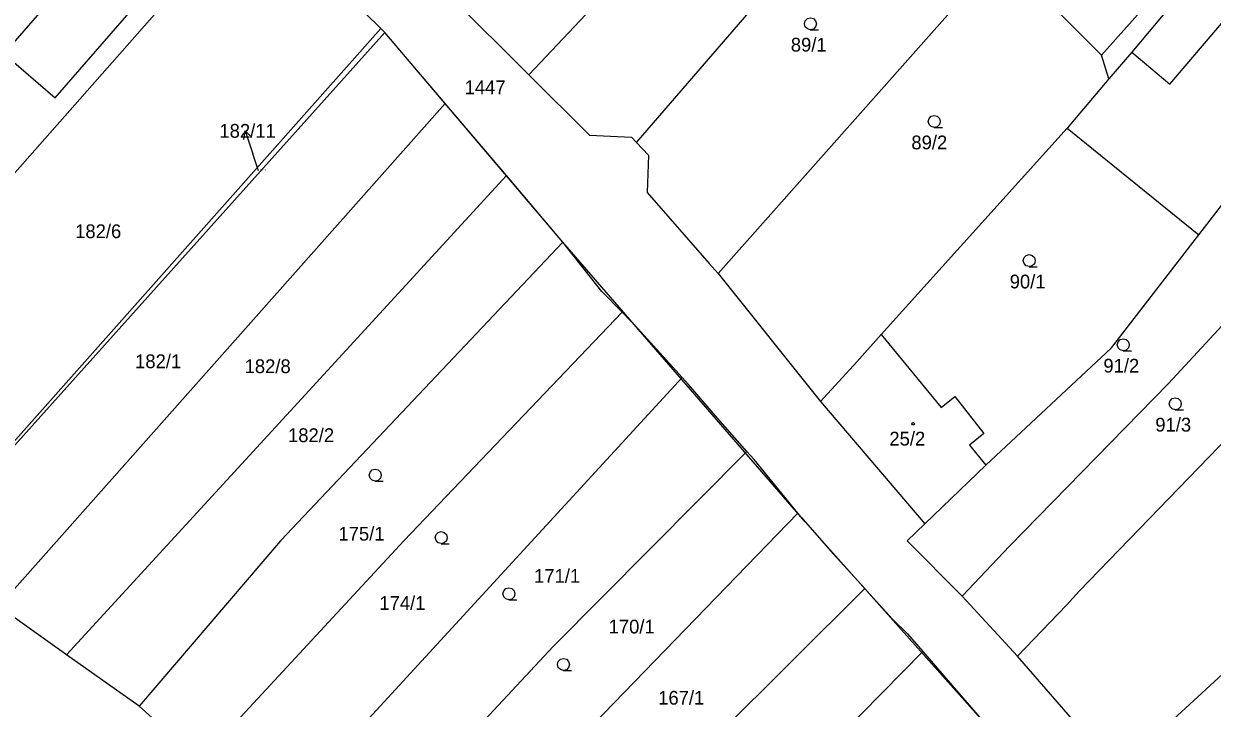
# Model space of a CAD drawing. Extents: x -580630 to -576196, y -1189024 to -1183567.
# Drawn here: x -578839.8 to -578693.1, y -1185934.4 to -1185849.8 of the extents above; entities that cross this region are included whole.
import ezdxf

# ---------------------------------------------------------------- set-up
doc = ezdxf.new("R2010")
doc.units = 0
for name, color, linetype in [('Vrstva 1', 7, 'Continuous'), ('Vrstva 16', 7, 'Continuous'), ('Vrstva 18', 7, 'Continuous'), ('Vrstva 19', 7, 'Continuous'), ('Vrstva 25', 7, 'Continuous'), ('Vrstva 4', 7, 'Continuous'), ('Vrstva 6', 7, 'Continuous'), ('Vrstva 63', 7, 'Continuous')]:
    doc.layers.add(name, color=color, linetype=linetype)

msp = doc.modelspace()

# ---------------------------------------------------------------- linework, layer by layer
at = {"layer": 'Vrstva 1'}
for p, q in [((-578764.13, -1185864.5), (-578737.1, -1185833.11)), ((-578715.81, -1185837.51), (-578754.08, -1185880.68)), ((-578835.92, -1185858.99), (-578820.89, -1185841.68)), ((-578795.7, -1185850.39), (-578805.13, -1185841.14)), ((-578842.2, -1185853.55), (-578833.43, -1185843.42)), ((-578706.73, -1185853.7), (-578716.76, -1185843.67)), ((-578788.11, -1185845.46), (-578777.42, -1185856.13)), ((-578700.88, -1185847.17), (-578706.73, -1185853.7)), ((-578770.38, -1185848.69), (-578777.42, -1185856.13)), ((-578698.7, -1185848.23), (-578703.01, -1185853.33)), ((-578852.69, -1185914.61), (-578795.7, -1185850.39)), ((-578795.19, -1185850.89), (-578795.7, -1185850.39)), ((-578787.75, -1185859.67), (-578795.19, -1185850.89)), ((-578703.01, -1185853.33), (-578705.83, -1185856.63)), ((-578842.2, -1185853.55), (-578835.92, -1185858.99)), ((-578705.83, -1185856.63), (-578706.73, -1185853.7)), ((-578777.42, -1185856.13), (-578769.96, -1185863.58)), ((-578705.83, -1185856.63), (-578710.99, -1185862.73)), ((-578842.9, -1185921.81), (-578787.75, -1185859.67)), ((-578780.2, -1185868.57), (-578787.75, -1185859.67)), ((-578769.96, -1185863.58), (-578764.76, -1185863.83)), ((-578733.93, -1185888.21), (-578710.99, -1185862.73)), ((-578710.99, -1185862.73), (-578694.74, -1185875.91)), ((-578764.76, -1185863.83), (-578764.13, -1185864.5)), ((-578764.13, -1185864.5), (-578762.66, -1185866.06)), ((-578762.66, -1185866.06), (-578762.84, -1185870.68)), ((-578773.22, -1185876.81), (-578780.2, -1185868.57)), ((-578762.84, -1185870.68), (-578755.18, -1185879.42)), ((-578694.74, -1185875.91), (-578690.52, -1185870.46)), ((-578773.22, -1185876.81), (-578808.09, -1185913.67)), ((-578768.42, -1185882.88), (-578773.22, -1185876.81)), ((-578705.5, -1185889.83), (-578694.74, -1185875.91)), ((-578698.48, -1185894.24), (-578682.73, -1185877.22)), ((-578755.18, -1185879.42), (-578754.08, -1185880.68)), ((-578754.08, -1185880.68), (-578741.42, -1185896.47)), ((-578765.91, -1185885.46), (-578768.42, -1185882.88)), ((-578792.88, -1185913.67), (-578765.91, -1185885.46)), ((-578763.99, -1185887.44), (-578765.91, -1185885.46)), ((-578758.52, -1185893.51), (-578763.99, -1185887.44)), ((-578736.94, -1185891.56), (-578733.93, -1185888.21)), ((-578733.93, -1185888.21), (-578726.54, -1185897.21)), ((-578709.49, -1185919.89), (-578678.5, -1185887.84)), ((-578721.03, -1185904.35), (-578705.5, -1185889.83)), ((-578736.94, -1185891.56), (-578741.42, -1185896.47)), ((-578809.25, -1185948.74), (-578758.52, -1185893.51)), ((-578757.73, -1185894.39), (-578758.52, -1185893.51)), ((-578754.41, -1185898.26), (-578757.73, -1185894.39)), ((-578718.1, -1185914.36), (-578698.48, -1185894.24)), ((-578726.54, -1185897.21), (-578724.86, -1185895.88)), ((-578724.86, -1185895.88), (-578721.28, -1185900.42)), ((-578741.42, -1185896.47), (-578728.55, -1185911.58)), ((-578750.52, -1185902.65), (-578754.41, -1185898.26)), ((-578721.28, -1185900.42), (-578723.02, -1185901.86)), ((-578723.02, -1185901.86), (-578721.03, -1185904.35)), ((-578774.44, -1185926.74), (-578750.52, -1185902.65)), ((-578749.63, -1185903.65), (-578750.52, -1185902.65)), ((-578744.22, -1185910.26), (-578749.63, -1185903.65)), ((-578728.55, -1185911.58), (-578721.03, -1185904.35)), ((-578779.5, -1185946.66), (-578744.22, -1185910.26)), ((-578743.75, -1185910.84), (-578744.22, -1185910.26)), ((-578743.75, -1185910.84), (-578743.33, -1185911.36)), ((-578743.33, -1185911.36), (-578739.84, -1185915.32)), ((-578730.75, -1185913.69), (-578728.55, -1185911.58)), ((-578808.09, -1185913.67), (-578825.52, -1185934.1)), ((-578818.03, -1185940.84), (-578792.88, -1185913.67)), ((-578730.75, -1185913.69), (-578723.95, -1185920.53)), ((-578723.95, -1185920.53), (-578718.1, -1185914.36)), ((-578739.84, -1185915.32), (-578735.97, -1185919.59)), ((-578698.38, -1185936.22), (-578676.74, -1185916.27)), ((-578760.08, -1185943.56), (-578735.97, -1185919.59)), ((-578735.97, -1185919.59), (-578735.36, -1185920.26)), ((-578735.36, -1185920.26), (-578732.55, -1185923.36)), ((-578723.95, -1185920.53), (-578717.12, -1185927.92)), ((-578711.05, -1185921.62), (-578709.49, -1185919.89)), ((-578834.5, -1185927.75), (-578842.9, -1185921.81)), ((-578717.12, -1185927.92), (-578711.05, -1185921.62)), ((-578732.55, -1185923.36), (-578730.7, -1185925.17)), ((-578730.7, -1185925.17), (-578728.8, -1185927.36)), ((-578801.53, -1185955.8), (-578774.44, -1185926.74)), ((-578825.52, -1185934.1), (-578834.5, -1185927.75)), ((-578751.63, -1185950.51), (-578728.8, -1185927.36)), ((-578728.8, -1185927.36), (-578721.26, -1185936.09)), ((-578706.23, -1185940.46), (-578717.12, -1185927.92)), ((-578818.03, -1185940.84), (-578825.52, -1185934.1))]:
    msp.add_line(p, q, dxfattribs=at)
at = {"layer": 'Vrstva 16'}
for p in [(-578812.458, -1185863.027), (-578810.79, -1185867.98)]:
    msp.add_line(p, (-578811.5, -1185865.87), dxfattribs=at)
msp.add_lwpolyline([(-578812.612, -1185864.134), (-578812.458, -1185863.027), (-578811.665, -1185863.815)], dxfattribs=at)
at = {"layer": 'Vrstva 25'}
for points in [[(-578742.67, -1185850.56), (-578743.05, -1185850.46), (-578743.32, -1185850.19), (-578743.42, -1185849.82), (-578743.32, -1185849.45), (-578743.05, -1185849.18), (-578742.68, -1185849.08), (-578742.31, -1185849.18), (-578742.04, -1185849.45), (-578741.94, -1185849.83), (-578742.04, -1185850.21), (-578742.31, -1185850.48), (-578742.69, -1185850.58), (-578741.69, -1185850.58)], [(-578727.37, -1185862.63), (-578727.75, -1185862.53), (-578728.02, -1185862.26), (-578728.12, -1185861.89), (-578728.02, -1185861.52), (-578727.75, -1185861.25), (-578727.38, -1185861.15), (-578727.01, -1185861.25), (-578726.74, -1185861.52), (-578726.64, -1185861.9), (-578726.74, -1185862.28), (-578727.01, -1185862.55), (-578727.39, -1185862.65), (-578726.39, -1185862.65)], [(-578715.65, -1185879.81), (-578716.03, -1185879.71), (-578716.3, -1185879.44), (-578716.4, -1185879.07), (-578716.3, -1185878.7), (-578716.03, -1185878.43), (-578715.66, -1185878.33), (-578715.29, -1185878.43), (-578715.02, -1185878.7), (-578714.92, -1185879.08), (-578715.02, -1185879.46), (-578715.29, -1185879.73), (-578715.67, -1185879.83), (-578714.67, -1185879.83)], [(-578704.04, -1185890.21), (-578704.42, -1185890.11), (-578704.69, -1185889.84), (-578704.79, -1185889.47), (-578704.69, -1185889.1), (-578704.42, -1185888.83), (-578704.05, -1185888.73), (-578703.68, -1185888.83), (-578703.41, -1185889.1), (-578703.31, -1185889.48), (-578703.41, -1185889.86), (-578703.68, -1185890.13), (-578704.06, -1185890.23), (-578703.06, -1185890.23)], [(-578697.62, -1185897.49), (-578698, -1185897.39), (-578698.27, -1185897.12), (-578698.37, -1185896.75), (-578698.27, -1185896.38), (-578698, -1185896.11), (-578697.63, -1185896.01), (-578697.26, -1185896.11), (-578696.99, -1185896.38), (-578696.89, -1185896.76), (-578696.99, -1185897.14), (-578697.26, -1185897.41), (-578697.64, -1185897.51), (-578696.64, -1185897.51)], [(-578796.39, -1185906.31), (-578796.77, -1185906.21), (-578797.04, -1185905.94), (-578797.14, -1185905.57), (-578797.04, -1185905.2), (-578796.77, -1185904.93), (-578796.4, -1185904.83), (-578796.03, -1185904.93), (-578795.76, -1185905.2), (-578795.66, -1185905.58), (-578795.76, -1185905.96), (-578796.03, -1185906.23), (-578796.41, -1185906.33), (-578795.41, -1185906.33)], [(-578788.23, -1185914.02), (-578788.61, -1185913.92), (-578788.88, -1185913.65), (-578788.98, -1185913.28), (-578788.88, -1185912.91), (-578788.61, -1185912.64), (-578788.24, -1185912.54), (-578787.87, -1185912.64), (-578787.6, -1185912.91), (-578787.5, -1185913.29), (-578787.6, -1185913.67), (-578787.87, -1185913.94), (-578788.25, -1185914.04), (-578787.25, -1185914.04)], [(-578779.88, -1185920.96), (-578780.26, -1185920.86), (-578780.53, -1185920.59), (-578780.63, -1185920.22), (-578780.53, -1185919.85), (-578780.26, -1185919.58), (-578779.89, -1185919.48), (-578779.52, -1185919.58), (-578779.25, -1185919.85), (-578779.15, -1185920.23), (-578779.25, -1185920.61), (-578779.52, -1185920.88), (-578779.9, -1185920.98), (-578778.9, -1185920.98)], [(-578773.15, -1185929.69), (-578773.53, -1185929.59), (-578773.8, -1185929.32), (-578773.9, -1185928.95), (-578773.8, -1185928.58), (-578773.53, -1185928.31), (-578773.16, -1185928.21), (-578772.79, -1185928.31), (-578772.52, -1185928.58), (-578772.42, -1185928.96), (-578772.52, -1185929.34), (-578772.79, -1185929.61), (-578773.17, -1185929.71), (-578772.17, -1185929.71)]]:
    msp.add_lwpolyline(points, dxfattribs=at)
msp.add_lwpolyline([(-578729.9, -1185899.07), (-578729.81, -1185899.22), (-578729.9, -1185899.37), (-578730.08, -1185899.37), (-578730.17, -1185899.22), (-578730.08, -1185899.07)], close=True, dxfattribs=at)
at = {"layer": 'Vrstva 4'}
for p, q in [((-578698.3, -1185857.27), (-578688.54, -1185845.78)), ((-578703.01, -1185853.33), (-578698.3, -1185857.27))]:
    msp.add_line(p, q, dxfattribs=at)
at = {"layer": 'Vrstva 6'}
for p, q in [((-578869.9, -1185901.16), (-578818.97, -1185843.35)), ((-578795.19, -1185850.89), (-578852.48, -1185914.77)), ((-578834.5, -1185927.75), (-578780.2, -1185868.57))]:
    msp.add_line(p, q, dxfattribs=at)
at = {"layer": 'Vrstva 63'}
for p, q in [((-578795.19, -1185850.89), (-578852.48, -1185914.77)), ((-578773.22, -1185876.81), (-578795.19, -1185850.89)), ((-578743.33, -1185911.36), (-578773.22, -1185876.81)), ((-578721.26, -1185936.09), (-578743.33, -1185911.36))]:
    msp.add_line(p, q, dxfattribs=at)

# ---------------------------------------------------------------- texts
at = {"layer": 'Vrstva 16'}
msp.add_text('182/11', height=1.7, dxfattribs=at).set_placement((-578815.629, -1185863.9))
at = {"layer": 'Vrstva 18'}
for s, height, p in [('89/1', 1.7, (-578745.093, -1185853.26)), ('1447', 1.7, (-578785.365, -1185858.52)), ('89/2', 1.7, (-578730.214, -1185865.33)), ('182/11', 0.2, (-578810.744, -1185867.98)), ('182/6', 1.7, (-578833.436, -1185876.3)), ('90/1', 1.7, (-578718.073, -1185882.51)), ('182/1', 1.7, (-578826.038, -1185892.36)), ('182/8', 1.7, (-578812.516, -1185892.97)), ('91/2', 1.7, (-578706.509, -1185892.91)), ('91/3', 1.7, (-578700.103, -1185900.19)), ('182/2', 1.7, (-578807.159, -1185901.49)), ('175/1', 1.7, (-578800.934, -1185913.66)), ('171/1', 1.7, (-578776.789, -1185918.87)), ('174/1', 1.7, (-578795.887, -1185922.21)), ('170/1', 1.7, (-578767.584, -1185925.13)), ('167/1', 1.7, (-578761.467, -1185933.92))]:
    msp.add_text(s, height=height, dxfattribs=at).set_placement(p)
at = {"layer": 'Vrstva 19'}
msp.add_text('25/2', height=1.7, dxfattribs=at).set_placement((-578732.928, -1185901.92))

doc.saveas('drawing.dxf')
